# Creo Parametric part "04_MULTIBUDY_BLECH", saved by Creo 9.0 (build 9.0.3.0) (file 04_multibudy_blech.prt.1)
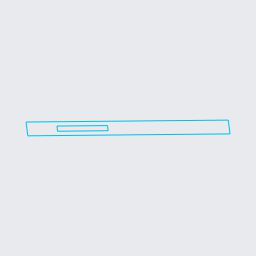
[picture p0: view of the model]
Units: millimeter Kilogram Sec (mmKs); MM, KILOGRAM, SECS
Materials in the file: S235JRG2

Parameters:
  BENENNUNG = "XXX"
  DATUM = "XX.XX.XX"
  ERSTELLER = "ARINDA"
  TEILETYP = "Fertigungsteil"
  PTC_MASTER_MATERIAL = "S235JRG2"
  SELECT_EN_NAME = "S235JRG2"
  SELECT_DIN_NAME = "RSt37-2"
  SELECT_DIN_NUMBER = "1.0038"
  SELECT_ASTM_NAME = "A 283 M Grade 2"
  MATERIAL_GROUP = "ME_ST_Baustahl"
  STANDARD_EN_DELIVERYSPEC = "DIN EN 10025"
  STANDARD_DIN_DELIVERYSPEC = "DIN 17100"

Other parameters: MASSE

Created from: ARINDA-STARTTEIL.PRT

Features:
  1. coordinate system "CS0"
  2. datum plane "DTM1", "T_RECHTS_Y-Z"
  3. datum plane "DTM2", "T_OBEN_X-Z"
  4. datum plane "DTM3", "T_VORNE_X-Y"
  5. datum axis "T_X-ACHSE"
  6. datum axis "A_1"
  7. datum axis "A_2"
  8. sketch "Skizze 1"

Other named items: T_BASIC, T_Y-ACHSE, T_Z-ACHSE

Layers: 00_STD-ACHSEN, 00_STD-EBENEN, 00_STD-KOORDSYS, 01_KURVEN, KURVENELEMENTE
